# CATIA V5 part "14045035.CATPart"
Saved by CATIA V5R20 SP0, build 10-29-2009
Part number: 14045035
Definition: NONE
Nomenclature: 14045035
Source: Unknown
Description: 14045035
Bounding box of the stored display mesh (mm): x -17.5 to 70, y -36.5 to 26.406, z -26.6 to 26.6
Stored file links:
  C:\Users\Utente\Desktop\IO LAVORO\3D X SITO CF\X SITO\PLASTICA\RF2\14045035.CATPart
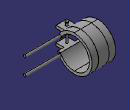
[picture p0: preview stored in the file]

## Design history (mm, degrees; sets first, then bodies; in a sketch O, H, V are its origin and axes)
Body1 "14045035" (main body)
  Solid1: solid without history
